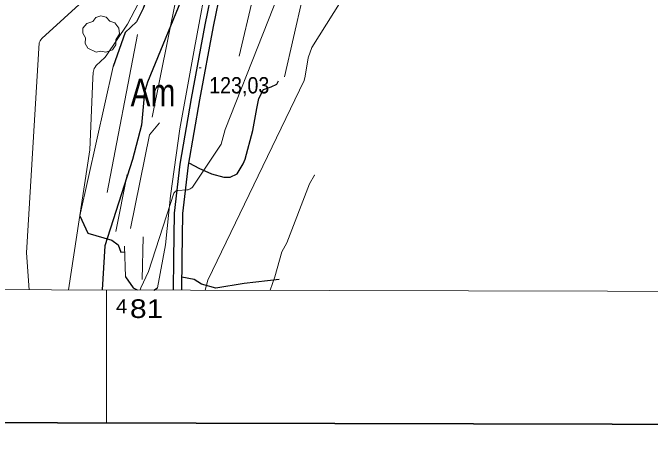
# Model space of a CAD drawing. Extents: x 480269 to 484877, y 4383588 to 4386804.
# Drawn here: x 480949.7 to 481291.4, y 4384064.3 to 4384291.8 of the extents above; entities that cross this region are included whole.
import ezdxf
from ezdxf.enums import TextEntityAlignment as Align

# ---------------------------------------------------------------- set-up
doc = ezdxf.new("R2010")
doc.units = 0
doc.header["$LTSCALE"] = 3.8
doc.linetypes.add('DOTTED', pattern=[1.5, 0.3, -1.2])
doc.linetypes.add('LONG_DASHED', pattern=[7.5, 6, -1.5])
for name, color, linetype, lineweight in [('1', 7, 'Continuous', 13), ('2', 7, 'DOTTED', 13), ('25', 7, 'LONG_DASHED', 25), ('29', 7, 'Continuous', 13), ('38', 7, 'Continuous', 25), ('51', 7, 'Continuous', 13), ('7', 7, 'Continuous', 13), ('8', 7, 'Continuous', 25), ('9', 7, 'Continuous', 13)]:
    doc.layers.add(name, color=color, linetype=linetype, lineweight=lineweight)
doc.layers.add('31', color=7, linetype='Continuous')

msp = doc.modelspace()

# ---------------------------------------------------------------- linework, layer by layer
at = {"layer": '1'}
msp.add_line((481000, 4384143.25), (481000, 4384071.9), dxfattribs=at)
at = {"layer": '1', "lineweight": 35}
msp.add_lwpolyline([(480458.83, 4386528.21), (484176.23, 4386519.28), (484170.33, 4384064.28), (480452.93, 4384073.22)], close=True, dxfattribs=at)
at = {"layer": '1'}
msp.add_lwpolyline([(480529.1, 4386456.6), (484105.5, 4386448.1), (484100.5, 4384135.8), (480523.1, 4384144.4)], close=True, dxfattribs=at)
at = {"layer": '25'}
msp.add_line((481025.27, 4384143.19), (481027.2, 4384144.42), dxfattribs=at)
for points in [[(481030.44, 4384320.01), (481022.87, 4384303.12), (481019.59, 4384294.04), (481016.04, 4384287.04), (481009.92, 4384281.17), (481003.51, 4384263.01)], [(481044.42, 4384211.13), (481049.39, 4384208.58), (481056.13, 4384205.51), (481062.8, 4384203.74), (481066.27, 4384203.65), (481069.94, 4384205.41), (481073.13, 4384210.91), (481074.21, 4384213.29), (481078.39, 4384228.63), (481080.41, 4384240.58), (481081.59, 4384245.91), (481084.08, 4384250.61), (481088.15, 4384252.08), (481091.21, 4384253.54), (481092.07, 4384255.32)], [(480985.69, 4384182.88), (480989.89, 4384173.66), (481002.8, 4384169.94), (481006.24, 4384167.36), (481007.66, 4384163.53), (481009.65, 4384163.58)], [(481010.05, 4384150.35), (481014.22, 4384144.32), (481016.33, 4384143.21)], [(481092.47, 4384148.79), (481073.77, 4384146.64), (481058.51, 4384144.22), (481050.88, 4384146.29), (481046.92, 4384148.75), (481040.23, 4384150)]]:
    msp.add_lwpolyline(points, dxfattribs=at)
at = {"layer": '29'}
msp.add_lwpolyline([(480994.46, 4384270.74), (480989.92, 4384272.86), (480988.51, 4384275.4), (480988.61, 4384278.38), (480987.24, 4384280.79), (480987.28, 4384283.54), (480989.44, 4384286.14), (480992.63, 4384287.14), (480994.28, 4384289.33), (480996.85, 4384290.16), (480999.71, 4384289.51), (481001.66, 4384287.24), (481004.47, 4384286.42), (481006.6, 4384283.57), (481006.84, 4384280.44), (481004.96, 4384277.29), (481004.96, 4384274.61), (481003.14, 4384272), (480999.52, 4384270.66), (480996.75, 4384271.29)], close=True, dxfattribs=at)
at = {"layer": '38'}
for points in [[(481151.17, 4384612.3), (481146.03, 4384591.73), (481140.41, 4384573.5), (481133.26, 4384558.67), (481122.94, 4384540.03), (481115.24, 4384524), (481107.55, 4384501.88), (481097.69, 4384471.66), (481087.91, 4384437.4), (481079.88, 4384404.63), (481070.58, 4384367.07), (481060.92, 4384325.61), (481052.67, 4384285.31), (481045.26, 4384245.88), (481039.17, 4384210.69), (481036.17, 4384184.48), (481035.75, 4384159.87), (481035.71, 4384143.17)], [(481087, 4384414.82), (481084.24, 4384403.56), (481074.94, 4384366.02), (481065.31, 4384324.65), (481057.08, 4384284.44), (481049.68, 4384245.09), (481043.61, 4384210.06), (481040.66, 4384184.18), (481040.24, 4384159.82), (481040.2, 4384143.16)]]:
    msp.add_lwpolyline(points, dxfattribs=at)
at = {"layer": '51'}
for p, q in [((481070.98, 4384268.56), (481101.35, 4384398.24)), ((481114.25, 4384340.9), (481095.31, 4384257.43)), ((481040.51, 4384315.34), (481024.37, 4384235.77)), ((481000.3, 4384195.44), (481016.5, 4384280.16)), ((481003.51, 4384263.01), (480985.69, 4384182.88)), ((481004.94, 4384174.57), (481010.91, 4384205.19)), ((481019.09, 4384148.92), (481019.55, 4384171.63)), ((481009.55, 4384166.76), (481010.05, 4384150.35))]:
    msp.add_line(p, q, dxfattribs=at)
for points in [[(481100.37, 4384496.61), (481089.01, 4384457.62), (481078.98, 4384420.43), (481067.18, 4384373.76), (481061.49, 4384348.77), (481055.17, 4384316.26), (481047.15, 4384272.92), (481039.18, 4384229.65), (481034.27, 4384193.67), (481031.58, 4384167.35), (481027.2, 4384144.42)], [(481028.25, 4384232.87), (481023.01, 4384226.34), (481012.8, 4384176.15)]]:
    msp.add_lwpolyline(points, dxfattribs=at)
at = {"layer": '7'}
msp.add_line((481049.6, 4384262.34), (481050.6, 4384262.34), dxfattribs=at)
at = {"layer": '8'}
msp.add_lwpolyline([(481041.19, 4384301.76), (481021.86, 4384254.56), (481020.32, 4384249.28), (481018.62, 4384231.62), (481013.92, 4384213.07), (480999, 4384166.94), (480997.56, 4384143.26)], dxfattribs=at)
at = {"layer": '9'}
for points in [[(481103.92, 4384331.65), (481063.53, 4384229.27)], [(481052.72, 4384143.13), (481054.22, 4384148.44), (481105.83, 4384255.44), (481106.37, 4384257.8), (481106.37, 4384257.88), (481106.34, 4384257.87), (481106.33, 4384257.86), (481108.03, 4384267.6), (481110.02, 4384273.11), (481125.63, 4384298.28), (481127.14, 4384299.8), (481142.77, 4384309.04), (481146.37, 4384311.8), (481153.47, 4384318.96), (481153.51, 4384318.97), (481153.53, 4384318.98), (481153.58, 4384319.01), (481153.61, 4384319.05), (481153.62, 4384319.06), (481153.62, 4384319.07), (481153.63, 4384319.11), (481159.96, 4384324.09), (481160.18, 4384324.27), (481163.18, 4384327.43)], [(480979.54, 4384143.3), (480990.95, 4384218.36), (480992.51, 4384256.74), (480992.78, 4384259.71), (480993.34, 4384261.87), (480993.78, 4384262.65), (480994.42, 4384263.46), (480998.95, 4384267.85), (480999.68, 4384268.7), (481011.16, 4384285.63), (481028.48, 4384318.9)], [(480958.53, 4384143.35), (480957.05, 4384163.11), (480963.89, 4384275.61), (480964.17, 4384276.41), (480964.34, 4384276.79), (480964.68, 4384277.37), (480965.24, 4384277.99), (481001.19, 4384310.92)], [(481063.53, 4384229.27), (481061.3, 4384221.36), (481046.07, 4384198.41), (481045.65, 4384198.01), (481045.37, 4384197.79), (481044.79, 4384197.42), (481044.13, 4384197.11), (481043.75, 4384196.98), (481043.04, 4384196.83), (481038.21, 4384196.54), (481037.93, 4384196.5), (481037.21, 4384196.28), (481036.74, 4384195.93), (481036.5, 4384195.68), (481036.08, 4384195.1), (481022.42, 4384153.04), (481018.28, 4384144.33), (481017.94, 4384143.21)], [(481087.56, 4384143.04), (481090.2, 4384150.2), (481093.97, 4384163.68), (481096.53, 4384168.57), (481108.66, 4384200.04), (481111.38, 4384204.7), (481111.59, 4384204.82)]]:
    msp.add_lwpolyline(points, dxfattribs=at)

# ---------------------------------------------------------------- texts
at = {"layer": '2'}
for s, height, width, p in [('4', 7.5, 1.1, (481004.98, 4384130.74)), ('81  ', 10, 1.2, (481012.48, 4384128.22))]:
    msp.add_text(s, height=height, rotation=359.862, dxfattribs=dict(at, width=width)).set_placement(p)
at = {"layer": '31', "width": 0.8}
msp.add_text('Am', height=15, dxfattribs=at).set_placement((481024.84, 4384241.57), align=Align.CENTER)
at = {"layer": '7', "width": 0.9}
msp.add_text('123,03', height=8.75, dxfattribs=at).set_placement((481054.97, 4384248.58))

doc.saveas('drawing.dxf')
